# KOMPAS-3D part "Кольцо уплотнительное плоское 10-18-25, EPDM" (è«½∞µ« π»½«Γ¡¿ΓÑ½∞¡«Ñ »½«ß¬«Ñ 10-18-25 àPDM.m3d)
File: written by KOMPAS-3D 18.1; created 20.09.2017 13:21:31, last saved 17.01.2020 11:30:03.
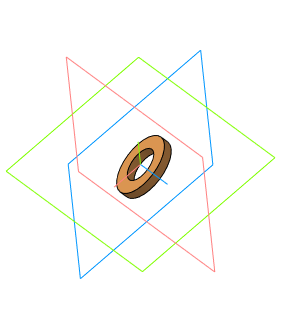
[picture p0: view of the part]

Document properties: Автор: Мирончук; Организация: Мирончук; Полное имя файла: D:\1 ПКИ 3D\РТИ\Кольца уплотнительные  плоские\Кольцо уплотнительное плоское 10-18-25 ЕPDM.m3d

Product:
- Part/product: Кольцо уплотнительное плоское 10-18-25  | designation EPDM
    Масса: 0.000562973
    Раздел спецификации: Прочие изделия
  - Component: Кольцо уплотнительное плоское / 10-18-25 ЕPDM  | Раздел спецификации: Прочие изделия
- Part/product: Кольцо уплотнительное плоское 10-18-25  | designation Viton
    Масса: 0.000562973
    Раздел спецификации: Прочие изделия

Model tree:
1. Эскиз:1
2. Операция выдавливания:1
     Расстояние 1 = 2.5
